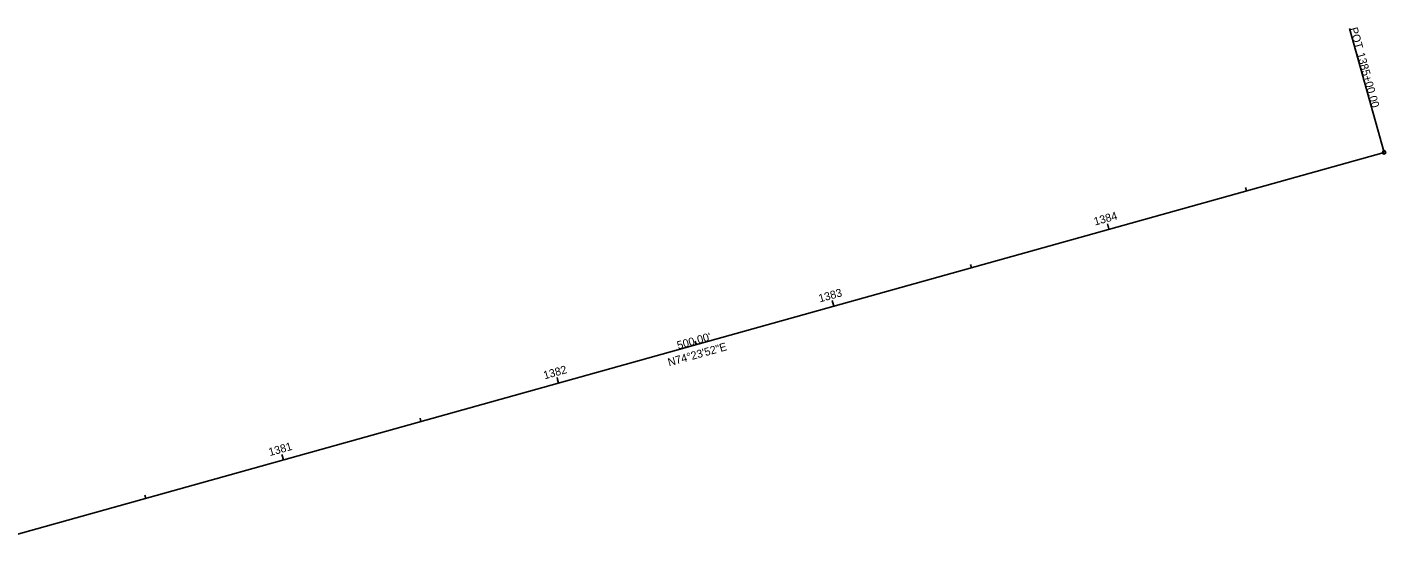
# Model space of a CAD drawing. Extents: x 153500 to 156291, y 370917 to 372075.
# Drawn here: x 155815.5 to 156291, y 371896.4 to 372074.7 of the extents above; entities that cross this region are included whole.
import ezdxf

# ---------------------------------------------------------------- set-up
doc = ezdxf.new("R2010")
doc.units = 0
for name, color, linetype in [('GE_X_Alignment', 7, 'Continuous'), ('GE_X_Alignment_1000_Stations', 7, 'Continuous'), ('GE_X_Alignment_100_Stations', 7, 'Continuous'), ('GE_X_Alignment_500_Stations', 7, 'Continuous')]:
    doc.layers.add(name, color=color, linetype=linetype)

msp = doc.modelspace()

# ---------------------------------------------------------------- linework, layer by layer
at = {"layer": 'GE_X_Alignment'}
msp.add_line((155808.83, 371896.43), (156290.4, 372030.91), dxfattribs=at)
at = {"layer": 'GE_X_Alignment_1000_Stations'}
msp.add_line((156290.4, 372030.91), (156278.3, 372074.25), dxfattribs=at)
msp.add_circle((156290.4, 372030.91), 0.6, dxfattribs=at)
at = {"layer": 'GE_X_Alignment_100_Stations'}
for p, q in [((156290.4, 372030.91), (156278.3, 372074.25)), ((156242.25, 372017.46), (156241.93, 372018.62)), ((156194.09, 372004.01), (156193.56, 372005.94)), ((156145.94, 371990.57), (156145.61, 371991.72)), ((156097.78, 371977.12), (156097.24, 371979.04)), ((156049.62, 371963.67), (156049.3, 371964.83)), ((156001.46, 371950.22), (156000.93, 371952.15)), ((155953.31, 371936.77), (155952.98, 371937.93)), ((155905.15, 371923.33), (155904.61, 371925.25)), ((155856.99, 371909.88), (155856.67, 371911.03))]:
    msp.add_line(p, q, dxfattribs=at)
msp.add_circle((156290.4, 372030.91), 0.6, dxfattribs=at)
at = {"layer": 'GE_X_Alignment_500_Stations'}
for p, q in [((156290.4, 372030.91), (156278.3, 372074.25)), ((156194.09, 372004.01), (156193.77, 372005.17)), ((156097.78, 371977.12), (156097.46, 371978.27)), ((156001.46, 371950.22), (156001.14, 371951.38)), ((155905.15, 371923.33), (155904.83, 371924.48))]:
    msp.add_line(p, q, dxfattribs=at)
msp.add_circle((156290.4, 372030.91), 0.6, dxfattribs=at)

# ---------------------------------------------------------------- texts
at = {"layer": 'GE_X_Alignment_1000_Stations'}
for s, rotation, p in [('POT', 285.6022, (156278.36, 372074.23)), ('1385+00.00', 285.6022, (156280.81, 372065.44)), ("500.00'", 15.6022, (156043.36, 371961.97)), ('N74°23\'52"E', 15.6022, (156040.14, 371956.04))]:
    msp.add_text(s, height=2.8, rotation=rotation, dxfattribs=at).set_placement(p)
at = {"layer": 'GE_X_Alignment_100_Stations'}
for s, rotation, p in [('POT', 285.6022, (156278.36, 372074.23)), ('1385+00.00', 285.6022, (156280.81, 372065.44)), ('1384', 15.6022, (156189.24, 372005.3)), ('1383', 15.6022, (156092.9, 371978.4)), ("500.00'", 15.6022, (156043.36, 371961.97)), ('N74°23\'52"E', 15.6022, (156040.14, 371956.04)), ('1382', 15.6022, (155996.58, 371951.5)), ('1381', 15.6022, (155900.42, 371924.65))]:
    msp.add_text(s, height=2.8, rotation=rotation, dxfattribs=at).set_placement(p)
at = {"layer": 'GE_X_Alignment_500_Stations'}
for s, rotation, p in [('POT', 285.6022, (156278.36, 372074.23)), ('1385+00.00', 285.6022, (156280.81, 372065.44)), ("500.00'", 15.6022, (156043.36, 371961.97)), ('N74°23\'52"E', 15.6022, (156040.14, 371956.04))]:
    msp.add_text(s, height=2.8, rotation=rotation, dxfattribs=at).set_placement(p)

doc.saveas('drawing.dxf')
